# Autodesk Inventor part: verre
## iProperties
Created: 2011-01
Part Number: verre
Document SubType Name: Modeling
Designer: eric
Density: 1 g/cm^3
Mass: 0.447908 g
Surface Area: 9.81953 cm^2
Volume: 0.447908 cm^3
Author: eric
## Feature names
1. Base1
